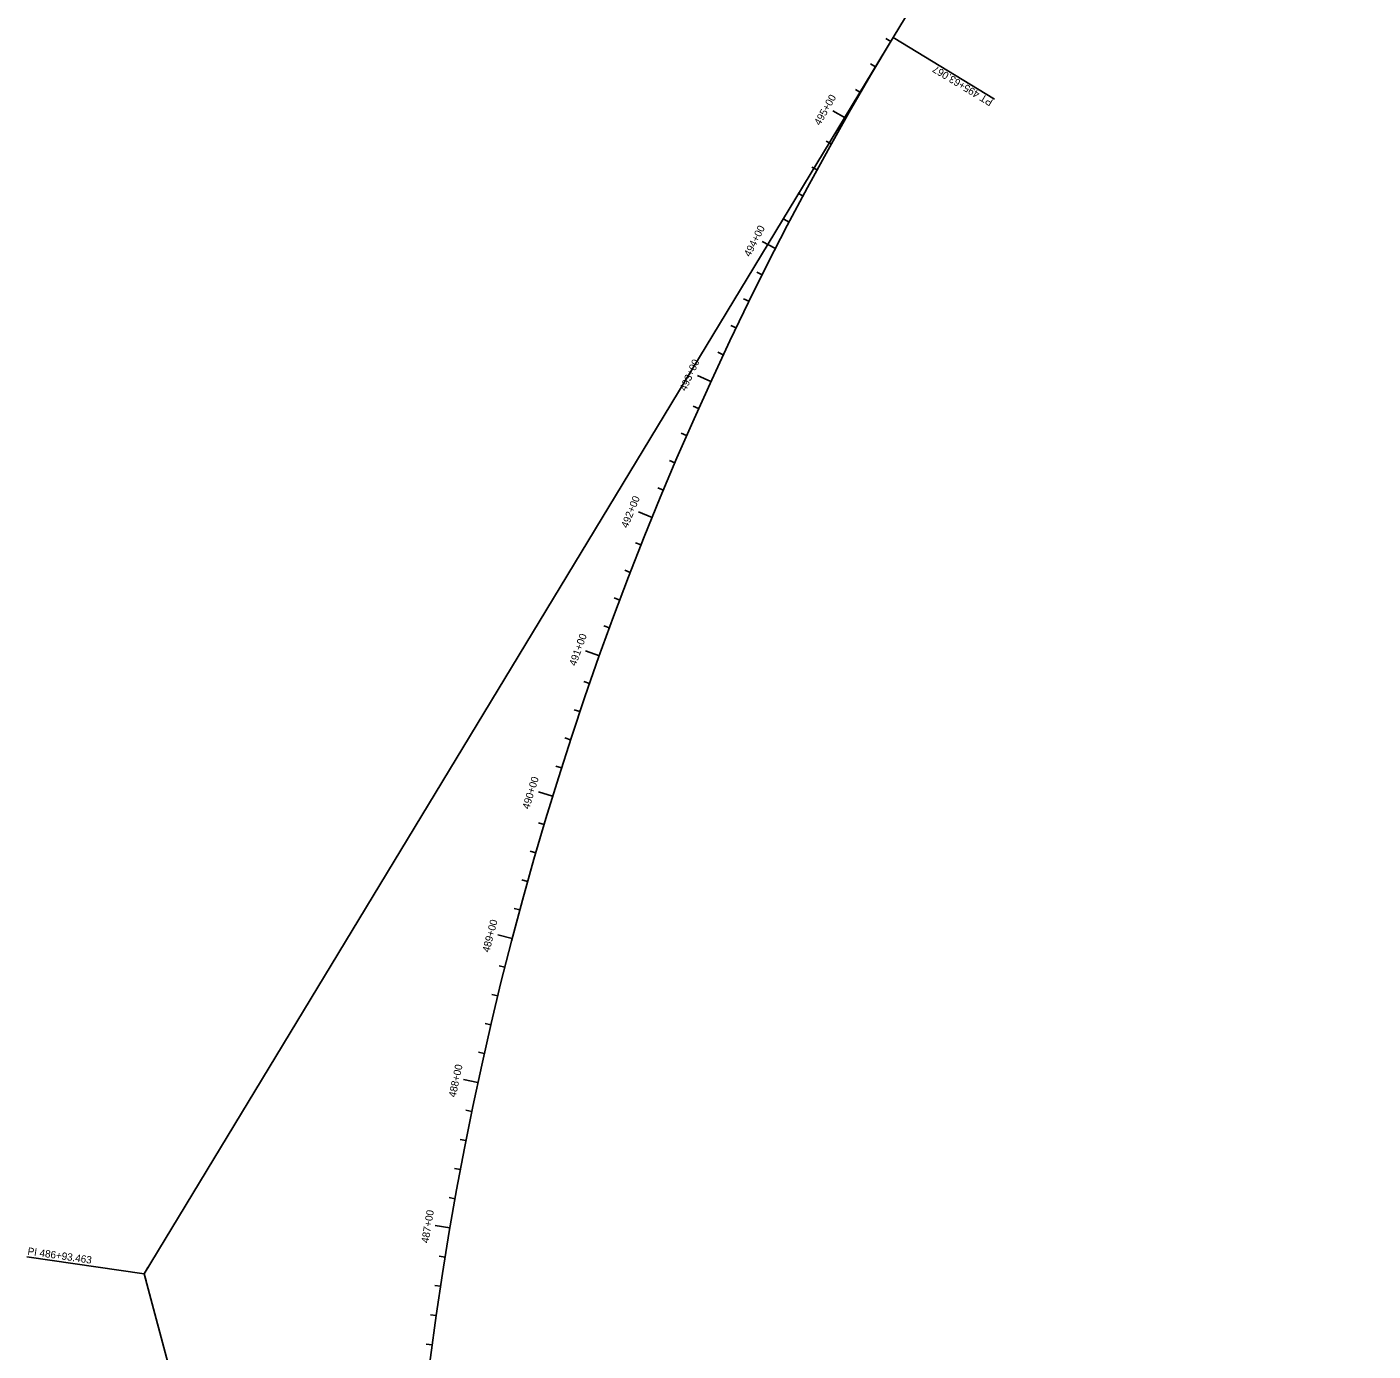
# Model space of a CAD drawing. Extents: x 187748 to 191086, y 249974 to 259749.
# Drawn here: x 189022 to 189932, y 255270 to 256164 of the extents above; entities that cross this region are included whole.
import ezdxf

# ---------------------------------------------------------------- set-up
doc = ezdxf.new("R2010")
doc.units = 0
doc.layers.add('BORDER', color=7, linetype='Continuous')

msp = doc.modelspace()

# ---------------------------------------------------------------- linework, layer by layer
at = {"layer": 'BORDER'}
for p, q in [((189607.44, 256156.93), (189931.65, 256692.02)), ((189605.86, 256154.3), (189602.43, 256156.37)), ((189607.44, 256156.93), (189675.86, 256115.47)), ((189595.59, 256137.14), (189592.15, 256139.18)), ((189585.47, 256119.88), (189582.01, 256121.89)), ((189575.51, 256102.54), (189566.82, 256107.49)), ((189565.7, 256085.12), (189562.2, 256087.07)), ((189556.03, 256067.61), (189552.52, 256069.52)), ((189546.53, 256050.01), (189543, 256051.9)), ((189537.17, 256032.33), (189533.63, 256034.19)), ((189527.97, 256014.57), (189519.08, 256019.13)), ((189518.93, 255996.74), (189515.36, 255998.53)), ((189510.04, 255978.82), (189506.45, 255980.58)), ((189501.31, 255960.82), (189497.71, 255962.56)), ((189492.74, 255942.76), (189489.12, 255944.46)), ((189484.32, 255924.61), (189475.23, 255928.78)), ((189476.07, 255906.4), (189472.42, 255908.03)), ((189467.97, 255888.11), (189464.3, 255889.71)), ((189460.03, 255869.75), (189456.35, 255871.32)), ((189452.25, 255851.33), (189448.56, 255852.87)), ((189444.64, 255832.83), (189435.37, 255836.6)), ((189437.18, 255814.28), (189433.46, 255815.75)), ((189429.89, 255795.65), (189426.16, 255797.09)), ((189422.76, 255776.97), (189419.02, 255778.38)), ((189415.79, 255758.22), (189412.04, 255759.6)), ((189408.99, 255739.41), (189399.57, 255742.77)), ((189402.35, 255720.54), (189398.57, 255721.86)), ((189395.88, 255701.62), (189392.09, 255702.9)), ((189389.57, 255682.64), (189385.77, 255683.89)), ((189383.43, 255663.61), (189379.62, 255664.82)), ((189377.45, 255644.52), (189367.9, 255647.47)), ((189371.65, 255625.38), (189367.81, 255626.53)), ((189366, 255606.2), (189362.16, 255607.31)), ((189360.53, 255586.96), (189356.68, 255588.04)), ((189355.22, 255567.68), (189351.36, 255568.72)), ((189350.09, 255548.35), (189340.41, 255550.87)), ((189345.12, 255528.98), (189341.24, 255529.95)), ((189340.32, 255509.56), (189336.43, 255510.5)), ((189335.69, 255490.1), (189331.79, 255491.01)), ((189331.23, 255470.61), (189327.33, 255471.48)), ((189326.94, 255451.07), (189317.16, 255453.17)), ((189322.82, 255431.5), (189318.9, 255432.31)), ((189318.87, 255411.89), (189314.95, 255412.67)), ((189315.1, 255392.25), (189311.17, 255392.99)), ((189311.49, 255372.58), (189307.56, 255373.29)), ((189308.06, 255352.88), (189298.2, 255354.55)), ((189101.52, 255321.91), (189022.33, 255333.23)), ((189304.8, 255333.15), (189300.85, 255333.78)), ((189101.52, 255321.91), (189104.11, 255326.19)), ((189101.52, 255321.91), (189102.81, 255317.08)), ((189301.71, 255313.39), (189297.76, 255313.99)), ((189298.79, 255293.6), (189294.83, 255294.17)), ((189296.05, 255273.79), (189292.09, 255274.32))]:
    msp.add_line(p, q, dxfattribs=at)
msp.add_lwpolyline([(189353.18, 254378.57), (189101.52, 255321.91), (189607.44, 256156.93)], dxfattribs=at)
msp.add_arc((191567.58, 254969.32), 2291.84, 148.78914, 194.93717, dxfattribs=at)

# ---------------------------------------------------------------- texts
for s, rotation, p in [('PT 495+63.067', 148.78911, (189675.35, 256114.62)), ('495+00', 60.36578, (189558.07, 256097.18)), ('494+00', 62.86577, (189510.79, 256008.45)), ('493+00', 65.36576, (189467.42, 255917.75)), ('492+00', 67.86575, (189428.05, 255825.24)), ('491+00', 70.36574, (189393.1, 255732.06)), ('490+00', 72.86573, (189361.54, 255635.32)), ('489+00', 75.36572, (189334.64, 255538.65)), ('488+00', 77.86572, (189311.94, 255440.75)), ('487+00', 80.36571, (189293.56, 255342.33)), ('PI 486+93.463', 351.86315, (189022.51, 255334.8))]:
    msp.add_text(s, height=5, rotation=rotation, dxfattribs=at).set_placement(p)

doc.saveas('drawing.dxf')
